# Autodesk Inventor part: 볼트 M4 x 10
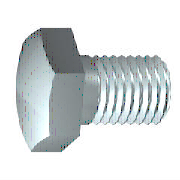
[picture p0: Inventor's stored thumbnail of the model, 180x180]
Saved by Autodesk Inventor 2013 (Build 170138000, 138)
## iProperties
Created: 2012-02
Part Number: 볼트 M4 x 10
Material: 스테인리스강
Description: 6각 머리 나사
Document SubType Name: Modeling
Standard: ISO 4017
Designer: mduedu
Standard Revision: Third edition 1999-08-15
Standards Organization: ISO
Language: ko-KR
Size Designation: M4 x 10
Categories: <MemberInstance><Categories><Category DisplayName="조임쇠" InternalName="e4da775c-781d-43d5-af7c-5136215cf5a6" Mnemonic="FSTN"><Category DisplayName="볼트" InternalN
Density: 8.08 g/cm^3
Mass: 1.91889 g
Surface Area: 2.7092 cm^2
Volume: 0.237486 cm^3
IsCustomPart: 0
Author: mduedu
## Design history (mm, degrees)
sketch "스케치1"
  geometry: L1 (0, 3.015)-(0, 2); L2 (2.1, 2)-(10, 2); L3 (10, 2)-(10, 0); L4 (10, 0)-(-0.4, 0); L5 (-2.48, 0)-(12.08, 0) reference; L6 (-0.4, 0)-(-0.4, 3.015); L7 (-0.4, 3.015)-(0, 3.015); L8 (2.1, 2)-(1.67, 2); L9 (1.67, 2)-(0, 2); L10 (0, -0.603)-(0, 3.618) reference
  constraints: 16 end point, 2 collinear, 2 perpendicular, 1 parallel
  dimensions: "d0" = 10 distance between parallel lines of L3 L1 (= NLG); "d1" = 7.9 distance from line of L2.start L3 (= GEL); "d2" = 4 diameter of L2 L4 (= GD); "d9" = 0.4001 distance between parallel lines of L6 L1 (computed from SD); "d10" = 6.03 diameter of L7 L4 (= SD2); "d13" = 0.42952 distance of L2.start L8.end (computed from GAL); "d14" = 4 diameter of L9 L4 (= BDM)
revolve "본체" sketch "스케치1" stored, may be unused: angle "d12" = 90 deg
sketch "스케치2"
  geometry: L1 (0, 4.041)-(3.5, 2.021); L2 (3.5, 2.021)-(3.5, -2.021); L3 (3.5, -2.021)-(0, -4.041); L4 (0, -4.041)-(-3.5, -2.021); L5 (-3.5, -2.021)-(-3.5, 2.021); L6 (-3.5, 2.021)-(0, 4.041); 2 further points
  constraints: 12 end point, 1 coincident, 1 vertical, 11 other
  dimensions: "d11" = 7 distance between parallel lines of L5 L2 (= SW)
extrude "머리" join sketch "스케치2" distance "d3" = 2.4 (= KOH - SD); taper "d4" = 0 deg
sketch "스케치4"
  geometry: L1 (-2.8, 3.5)-(-2.8, 4.041); L2 (-2.8, 4.041)-(-2.487, 4.041); L3 (-2.487, 4.041)-(-2.8, 3.5); L4 (-3.28, 0)-(0.08, 0) reference; L5 (-0.4, 4.041)-(-2.8, 4.041) reference; L6 (-2.8, 2.021)-(-2.8, 4.041) reference
  constraints: 6 end point, 2 collinear, 1 perpendicular, 1 vertical
  dimensions: "d5" = 30 deg angle of L3 L1 (= ANG1); "d19" = 7 diameter of L1.start L4 (= SW0)
revolve "모따기1" sketch "스케치4" stored, may be unused: angle "d21" = 90 deg
workplane "Work Plane1"
body "Solid1"
feature "스레드" dims "d15" = 7.9 (= GEL), "d16" = 0
chamfer "모따기2" distance "d6" = 0.42941 (= -0.5 x SPD + 0.5 x GD); stored, may be unused: second distance "d7" = 0.42952 (computed from GUL), angle "d55" = 45 deg
other parameters: "NLG" = 10 [user parameter; used in 1 equation term], "GD" = 4 (= NND) [user parameter; used in 2 equation terms], "BDM" = 4 (= NND) [user parameter; used in 1 equation term], "KOH" = 2.8 [user parameter; used in 1 equation term], "GEL" = 7.9 [user parameter; used in 2 equation terms], "SW" = 7 [user parameter; used in 2 equation terms], "SW0" = 7 (= SW) [user parameter; used in 1 equation term], "SPD" = 3.14117 (= NND - 1.2269 x PTC) [user parameter; used in 1 equation term], "SD2" = 6.03 [user parameter; used in 2 equation terms], "SD" = 0.4 [user parameter; used in 2 equation terms], "ANG1" = 30 deg [user parameter; used in 1 equation term], "GAL" = 0.42941 (= 0.61345 x PTC) [user parameter; used in 1 equation term], "GUL" = 0.42941 (= 0.61345 x PTC) [user parameter; used in 1 equation term], "d8" = 0, "RR" = 0.2 [user parameter], "d57" = 0, "d58" = 0, "TPU" = 14.28571 (computed from PTC) [user parameter], "GD1" = 3.14117 (= THREADDIA - 1.2269 x PTC) [user parameter], "THREADDIA" = 4 [user parameter; used in 1 equation term], "SDH" = 6.03 (= SD2) [user parameter], "SDHG" = 2.1 [user parameter], "TOA" = 30 deg [user parameter], "PTC" = 0.7 [user parameter; used in 5 equation terms], "NND" = 4 [user parameter; used in 3 equation terms], "E0" = 8.085 [user parameter]
